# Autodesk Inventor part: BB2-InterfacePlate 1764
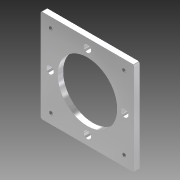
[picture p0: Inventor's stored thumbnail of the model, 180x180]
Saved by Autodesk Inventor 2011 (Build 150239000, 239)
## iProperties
Company: FirstCadLibrary
Shininess: 64.0
Length Units: 11269
Angle Units: 11279
Time Units: 11290
Mass Units: 11283
Length Display Precision: 3
Angle Display Precision: 2
Compacted: True
Part Number: BB2-InterfacePlate 1764
Document SubType Name: Modeling
Created: 2007-01
Material: Aluminum-6061
Designer: Ed Sparks
Catalog Web Link: www.banebots.com
Vendor: BaneBots
Mass: 26.5594 g
Surface Area: 70.4801 cm^2
Volume: 9.80051 cm^3
Density: 2.71 g/cm^3
Density: 0.0
Volumn: 0.0
Area: 0.0
PropertySet Name: Model Information
Control State: 0
Master: False
Checked Out: False
Author: Ed Sparks
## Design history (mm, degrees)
sketch "Sketch1"
  geometry: L1 (-31.75, 31.75)-(31.75, 31.75); L2 (31.75, 31.75)-(31.75, -31.75); L3 (31.75, -31.75)-(-31.75, -31.75); L4 (-31.75, -31.75)-(-31.75, 31.75); L5 (0, 0)-(31.75, 0); L6 (0, 0)-(-31.75, 0); L7 (0, 0)-(0, 31.75); L8 (0, 0)-(0, -31.75)
  constraints: 16 end point, 4 midpoint, 2 collinear, 2 parallel, 1 horizontal, 1 perpendicular, 1 other
  dimensions: "d0" = 63.5 distance of L1.start L1.end; "d1" = 63.5 distance of L1.end L2.end
extrude "Extrusion1" new body sketch "Sketch1" stored distance "d2" = 3.7; taper "d3" = 0 deg
sketch "Sketch2"
  geometry: 1 further point
hole "Hole1" sketch "Sketch2" at (0, 0) diameter "d4" = 40.45; stored, may be unused: countersink angle "d8" = 82 deg, drill point angle "d10" = 118 deg; dims "d5" = 6, "d6" = 4, "d7" = 2, "d9" = 8
sketch "Sketch3"
  geometry: C1 r 20.225 at (0, 0) reference; 1 further point
  constraints: 1 vertical alignment
  dimensions: "d11" = 25.4 distance of point (0, 25.4) C1.centre
hole "Hole2" sketch "Sketch3" at (0, 25.4) diameter "d12" = 5; stored, may be unused: countersink angle "d16" = 82 deg, drill point angle "d18" = 118 deg; dims "d13" = 6, "d14" = 4, "d15" = 2, "d17" = 8
pattern_circular "Circular Pattern1" dims angle "d21" = 360 deg
sketch "Sketch4"
  geometry: C1 r 2.5 at (-25.4, 0) reference; C2 r 2.5 at (0, 25.4) reference; 1 further point
  dimensions: "d24" = 24.82719 vertical distance of C1.centre point (-25, 24.827); "d25" = 25 horizontal distance of C2.centre point (-25, 24.827)
hole "Hole3" sketch "Sketch4" at (-25, 24.827) diameter "d26" = 2.459; stored, may be unused: countersink angle "d30" = 82 deg, drill point angle "d32" = 118 deg; dims "d27" = 6, "d28" = 4, "d29" = 2, "d31" = 8
pattern_circular "Circular Pattern2" dims angle "d35" = 360 deg
fillet "Fillet1" dims "d36" = 1
body "Solid1"
